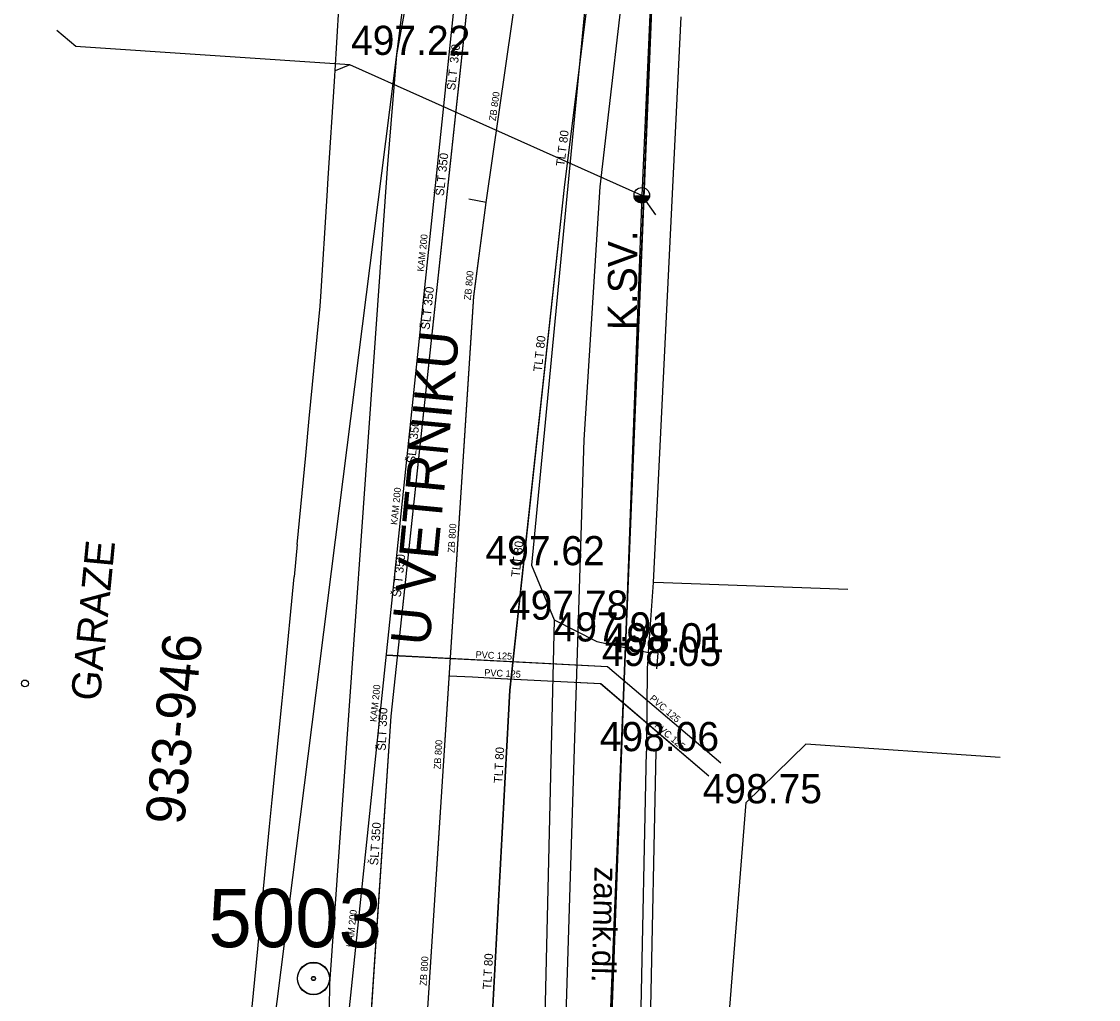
# Model space of a CAD drawing. Extents: x -669642 to -669119, y -1131006 to -1130466.
# Drawn here: x -669414.71 to -669387.02, y -1130677.82 to -1130652.68 of the extents above; entities that cross this region are included whole.
import ezdxf

# ---------------------------------------------------------------- set-up
doc = ezdxf.new("R2010")
doc.units = 0
for name, color, linetype in [('G_Bod_tecka', 7, 'Continuous'), ('G_Bod_vyska', 7, 'Continuous'), ('G_Bodove_pole', 7, 'Continuous'), ('G_Budovy-znacky', 7, 'Continuous'), ('G_Budovy_Objekty', 7, 'Continuous'), ('G_Budovy_vstupy', 7, 'Continuous'), ('G_Cisla_jina', 7, 'Continuous'), ('G_Plochy_zpevnene', 7, 'Continuous'), ('G_Ploty', 7, 'Continuous'), ('G_Ploty_vstupy', 7, 'Continuous'), ('G_Popisy_Nazvy', 7, 'Continuous'), ('G_Popisy_povrchu', 7, 'Continuous'), ('G_Poznamky_odkaz', 7, 'Continuous'), ('G_Site-Sloupy', 7, 'Continuous'), ('G_Z_ELsilove_nadz_kotovane', 7, 'Continuous'), ('G_Z_ELsilove_podz_kotovane', 7, 'Continuous'), ('G_Z_KANAL_podz_kotovane', 7, 'Continuous'), ('G_Z_KANAL_podz_priblizne', 7, 'Continuous'), ('G_Z_PLYNY_podz_geodeticky', 7, 'Continuous'), ('G_Z_SPOJE_nadz_kotovane', 7, 'Continuous'), ('G_Z_VODA_podz_kotovane', 7, 'Continuous'), ('Vrstva 11', 7, 'Continuous'), ('Vrstva 12', 7, 'Continuous'), ('Vrstva 26', 7, 'Continuous'), ('Vrstva 3', 7, 'Continuous'), ('Vrstva 4', 7, 'Continuous'), ('Vrstva 5', 7, 'Continuous'), ('Vrstva 9', 7, 'Continuous')]:
    doc.layers.add(name, color=color, linetype=linetype)

msp = doc.modelspace()

# ---------------------------------------------------------------- linework, layer by layer
at = {"layer": 'G_Bod_tecka'}
for p, q in [((-669405.07, -1130653.54), (-669405.07, -1130653.54)), ((-669401.6, -1130666.66), (-669401.6, -1130666.66)), ((-669401.01, -1130668.06), (-669401.01, -1130668.06)), ((-669399.92, -1130668.62), (-669399.92, -1130668.62)), ((-669398.59, -1130668.9), (-669398.59, -1130668.9)), ((-669398.6, -1130669.25), (-669398.6, -1130669.25)), ((-669398.64, -1130671.44), (-669398.64, -1130671.44)), ((-669396.03, -1130672.78), (-669396.03, -1130672.78))]:
    msp.add_line(p, q, dxfattribs=at)
at = {"layer": 'G_Bodove_pole'}
for centre, radius in [((-669407.2, -1130677.28), 0.412), ((-669407.2, -1130677.29), 0.412), ((-669407.2, -1130677.28), 0.05), ((-669407.2, -1130677.29), 0.05)]:
    msp.add_circle(centre, radius, dxfattribs=at)
at = {"layer": 'G_Budovy-znacky'}
msp.add_circle((-669414.62, -1130669.699), 0.0875, dxfattribs=at)
at = {"layer": 'G_Budovy_Objekty'}
for p, q in [((-669406.66, -1130654.22), (-669406.61, -1130653.37)), ((-669406.85, -1130657.16), (-669406.82, -1130656.71)), ((-669407.03, -1130660), (-669407.01, -1130659.75)), ((-669407.06, -1130660.35), (-669407.03, -1130660)), ((-669407.4, -1130663.84), (-669407.31, -1130662.89)), ((-669407.62, -1130666.13), (-669407.7, -1130666.96)), ((-669408.01, -1130670.15), (-669407.95, -1130669.55)), ((-669396.08, -1130672.76), (-669394.54, -1130671.26)), ((-669389.55, -1130671.6), (-669394.54, -1130671.26)), ((-669408.33, -1130673.38), (-669408.26, -1130672.69)), ((-669396.63, -1130679.75), (-669396.08, -1130672.76)), ((-669408.63, -1130676.52), (-669408.57, -1130675.87))]:
    msp.add_line(p, q, dxfattribs=at)
at = {"layer": 'G_Budovy_vstupy'}
for p, q in [((-669406.61, -1130653.37), (-669406.46, -1130650.92)), ((-669406.82, -1130656.71), (-669406.66, -1130654.22)), ((-669407.01, -1130659.75), (-669406.85, -1130657.16)), ((-669407.31, -1130662.89), (-669407.06, -1130660.35)), ((-669407.62, -1130666.13), (-669407.4, -1130663.84)), ((-669407.95, -1130669.55), (-669407.7, -1130666.96)), ((-669408.26, -1130672.69), (-669408.01, -1130670.15)), ((-669408.57, -1130675.87), (-669408.33, -1130673.38)), ((-669408.87, -1130678.96), (-669408.63, -1130676.52))]:
    msp.add_line(p, q, dxfattribs=at)
at = {"layer": 'G_Plochy_zpevnene'}
for points in [[(-669403.74, -1130646.37), (-669404.42, -1130649.99), (-669405.07, -1130653.54)], [(-669400.06, -1130650.63), (-669401.6, -1130666.66)], [(-669405.07, -1130653.54), (-669405.31, -1130656.46)], [(-669405.31, -1130656.46), (-669406.79, -1130677.42)], [(-669401.6, -1130666.66), (-669401.01, -1130668.06)], [(-669401.01, -1130668.06), (-669401.52, -1130689.56), (-669401.73, -1130703.06)], [(-669401.01, -1130668.06), (-669399.92, -1130668.62)], [(-669399.92, -1130668.62), (-669398.59, -1130668.9)], [(-669406.79, -1130677.42), (-669407.03, -1130695.18)]]:
    msp.add_lwpolyline(points, dxfattribs=at)
at = {"layer": 'G_Ploty'}
for p, q in [((-669398.05, -1130658.69), (-669397.75, -1130652.56)), ((-669398.46, -1130667.1), (-669398.05, -1130658.69)), ((-669398.59, -1130668.9), (-669398.46, -1130667.1)), ((-669398.2, -1130667.11), (-669398.46, -1130667.1)), ((-669393.46, -1130667.28), (-669398.2, -1130667.11)), ((-669398.59, -1130668.9), (-669398.62, -1130669.3)), ((-669398.34, -1130668.92), (-669398.59, -1130668.9)), ((-669398.37, -1130669.32), (-669398.34, -1130668.92)), ((-669398.81, -1130679.62), (-669398.64, -1130671.44)), ((-669398.56, -1130679.63), (-669398.39, -1130671.44))]:
    msp.add_line(p, q, dxfattribs=at)
at = {"layer": 'G_Ploty_vstupy'}
msp.add_line((-669398.62, -1130669.3), (-669398.64, -1130671.44), dxfattribs=at)
at = {"layer": 'G_Site-Sloupy'}
msp.add_circle((-669398.76, -1130657.15), 0.2, dxfattribs=at)
for radius in [0.18, 0.16, 0.14, 0.12, 0.1, 0.08, 0.06, 0.04, 0.02]:
    msp.add_arc((-669398.76, -1130657.15), radius, 180, 0, dxfattribs=at)
at = {"layer": 'G_Z_ELsilove_nadz_kotovane'}
for points in [[(-669397.335, -1130624.981), (-669398.76, -1130657.15)], [(-669413.315, -1130653.325), (-669413.8, -1130652.911)], [(-669398.76, -1130657.15), (-669406.265, -1130653.792), (-669413.316, -1130653.324)], [(-669406.265, -1130653.792), (-669406.644, -1130653.951)], [(-669398.76, -1130657.15), (-669399.972, -1130690.325)], [(-669398.76, -1130657.15), (-669398.409, -1130657.65)]]:
    msp.add_lwpolyline(points, dxfattribs=at)
at = {"layer": 'G_Z_ELsilove_podz_kotovane'}
msp.add_lwpolyline([(-669397.44, -1130624.27), (-669398.48, -1130651.54), (-669400.06, -1130690.34), (-669400.27, -1130706.05), (-669396.56, -1130732.21), (-669391.83, -1130758.66)], dxfattribs=at)
at = {"layer": 'G_Z_KANAL_podz_kotovane'}
for p, q in [((-669407.69, -1130691.54), (-669402.63, -1130643.21)), ((-669402.76, -1130657.33), (-669403.21, -1130657.25)), ((-669405.54, -1130697.79), (-669403.08, -1130659.75))]:
    msp.add_line(p, q, dxfattribs=at)
for points in [[(-669403.08, -1130659.75), (-669402.76, -1130657.33), (-669401.92, -1130651.49)], [(-669396.73, -1130671.75), (-669399.64, -1130669.27), (-669405.33, -1130668.98)]]:
    msp.add_lwpolyline(points, dxfattribs=at)
at = {"layer": 'G_Z_KANAL_podz_priblizne'}
msp.add_lwpolyline([(-669397.04, -1130672.08), (-669399.82, -1130669.71), (-669402.38, -1130669.58), (-669403.11, -1130669.54), (-669403.71, -1130669.51)], dxfattribs=at)
at = {"layer": 'G_Z_PLYNY_podz_geodeticky'}
msp.add_lwpolyline([(-669393.28, -1130633.86), (-669394.49, -1130638.18), (-669399.08, -1130650.34), (-669399.84, -1130656.93), (-669400.25, -1130663.44), (-669400.87, -1130683.15), (-669400.96, -1130685.74), (-669400.98, -1130689.56)], dxfattribs=at)
at = {"layer": 'G_Z_SPOJE_nadz_kotovane'}
msp.add_lwpolyline([(-669403.46, -1130640.77), (-669408.34, -1130679.44)], dxfattribs=at)
at = {"layer": 'G_Z_VODA_podz_kotovane'}
for points in [[(-669387.02, -1130812.53), (-669389.23, -1130792.08), (-669391, -1130779.42), (-669391.97, -1130772.22), (-669392.06, -1130771.92), (-669391.97, -1130771.16), (-669393.13, -1130764.98), (-669393.69, -1130761.37), (-669394.75, -1130753.04), (-669396.24, -1130745.91), (-669399.34, -1130731.13), (-669400.46, -1130726.23), (-669400.61, -1130725.04), (-669400.78, -1130724.52), (-669402.59, -1130713.28), (-669402.7, -1130712.61), (-669402.95, -1130701.47), (-669402.25, -1130693.89), (-669402.71, -1130680.24), (-669402.15, -1130669.87), (-669400.75, -1130656.95), (-669398.85, -1130641.75)], [(-669403.09, -1130650.73), (-669405.21, -1130670.54), (-669406.48, -1130689.47), (-669407.14, -1130697.84), (-669406.32, -1130715.38), (-669403.7, -1130729.64), (-669400.71, -1130745.88), (-669399.15, -1130753.32), (-669398.52, -1130755.36), (-669396.1, -1130756.91), (-669395.09, -1130760.49), (-669394.09, -1130765.4), (-669391.66, -1130786.81), (-669388.98, -1130811.25)]]:
    msp.add_lwpolyline(points, dxfattribs=at)
at = {"layer": 'Vrstva 11'}
msp.add_lwpolyline([(-669396.732, -1130671.751), (-669399.639, -1130669.272), (-669405.328, -1130668.975)], dxfattribs=at)
at = {"layer": 'Vrstva 12'}
for p, q in [((-669407.692, -1130691.538), (-669402.628, -1130643.211)), ((-669402.76, -1130657.33), (-669403.205, -1130657.246)), ((-669405.541, -1130697.793), (-669403.077, -1130659.745))]:
    msp.add_line(p, q, dxfattribs=at)
msp.add_lwpolyline([(-669403.077, -1130659.745), (-669402.76, -1130657.33), (-669401.92, -1130651.49)], dxfattribs=at)
at = {"layer": 'Vrstva 26'}
for points in [[(-669387.019, -1130812.528), (-669389.231, -1130792.082), (-669391.001, -1130779.42), (-669391.97, -1130772.22), (-669392.06, -1130771.92), (-669391.97, -1130771.16), (-669393.133, -1130764.977), (-669393.689, -1130761.37), (-669394.75, -1130753.038), (-669396.244, -1130745.914), (-669399.343, -1130731.135), (-669400.461, -1130726.23), (-669400.612, -1130725.037), (-669400.78, -1130724.52), (-669402.594, -1130713.284), (-669402.695, -1130712.614), (-669402.948, -1130701.466), (-669402.247, -1130693.89), (-669402.705, -1130680.236), (-669402.147, -1130669.872), (-669400.746, -1130656.946), (-669398.853, -1130641.75)], [(-669403.087, -1130650.733), (-669405.214, -1130670.54), (-669406.476, -1130689.467), (-669407.14, -1130697.842), (-669406.32, -1130715.384), (-669403.695, -1130729.64), (-669400.705, -1130745.879), (-669399.153, -1130753.32), (-669398.519, -1130755.364), (-669396.099, -1130756.914), (-669395.09, -1130760.491), (-669394.091, -1130765.401), (-669391.664, -1130786.81), (-669388.978, -1130811.253)]]:
    msp.add_lwpolyline(points, dxfattribs=at)
at = {"layer": 'Vrstva 5'}
for p, q in [((-669398.48, -1130651.54), (-669400.06, -1130690.34)), ((-669400.06, -1130690.34), (-669398.48, -1130651.54))]:
    msp.add_line(p, q, dxfattribs=at)
at = {"layer": 'Vrstva 9'}
msp.add_lwpolyline([(-669397.04, -1130672.082), (-669399.817, -1130669.713), (-669402.384, -1130669.579), (-669403.109, -1130669.541), (-669403.709, -1130669.51)], dxfattribs=at)

# ---------------------------------------------------------------- texts
at = {"layer": 'G_Bod_vyska'}
for s, p in [('497.22', (-669406.236, -1130653.54)), ('497.62', (-669402.78, -1130666.66)), ('497.78', (-669402.176, -1130668.06)), ('497.91', (-669401.026, -1130668.62)), ('498.01', (-669399.716, -1130668.9)), ('498.05', (-669399.788, -1130669.25)), ('498.06', (-669399.841, -1130671.44)), ('498.75', (-669397.196, -1130672.78))]:
    msp.add_text(s, height=0.75, dxfattribs=at).set_placement(p)
at = {"layer": 'G_Bodove_pole'}
msp.add_text('5003', height=1.5, dxfattribs=at).set_placement((-669409.903, -1130676.48))
at = {"layer": 'G_Cisla_jina'}
msp.add_text('933-946', height=1, rotation=84.5231, dxfattribs=at).set_placement((-669410.529, -1130673.353))
at = {"layer": 'G_Popisy_Nazvy'}
msp.add_text('U VETRNIKU', height=1, rotation=84.5281, dxfattribs=at).set_placement((-669404.224, -1130668.754))
at = {"layer": 'G_Popisy_povrchu'}
msp.add_text('zamk.dl.', height=0.6, rotation=268.5879, dxfattribs=at).set_placement((-669399.975, -1130674.404))
at = {"layer": 'G_Poznamky_odkaz'}
for s, rotation, p in [('K.SV.', 89.7299, (-669398.887, -1130660.616)), ('GARAZE', 84.5231, (-669412.694, -1130670.167))]:
    msp.add_text(s, height=0.75, rotation=rotation, dxfattribs=at).set_placement(p)
at = {"layer": 'Vrstva 3'}
for s, rotation, p in [('ZB 800', 82.0565, (-669402.517, -1130655.248)), ('KAM 200', 84.0331, (-669404.365, -1130659.118)), ('ZB 800', 84.3076, (-669403.158, -1130659.852)), ('KAM 200', 84.0365, (-669405.048, -1130665.63)), ('ZB 800', 86.2642, (-669403.576, -1130666.347)), ('PVC 125', 357.0238, (-669403.037, -1130669.042)), ('PVC 125', 357.0051, (-669402.814, -1130669.503)), ('KAM 200', 84.0365, (-669405.58, -1130670.696)), ('PVC 125', 319.5149, (-669398.575, -1130670.11)), ('PVC 125', 319.5279, (-669398.45, -1130670.809)), ('ZB 800', 86.3021, (-669403.935, -1130671.91)), ('KAM 200', 84.0398, (-669406.186, -1130676.486)), ('ZB 800', 86.3047, (-669404.296, -1130677.474))]:
    msp.add_text(s, height=0.1755, rotation=rotation, dxfattribs=at).set_placement(p)
at = {"layer": 'Vrstva 4'}
for s, rotation, p in [('ŠLT  350', 83.8397, (-669403.559, -1130654.458)), ('TLT 80', 82.9439, (-669400.751, -1130656.412)), ('ŠLT 350', 83.9054, (-669403.85, -1130657.175)), ('ŠLT 350', 83.8769, (-669404.219, -1130660.613)), ('TLT 80', 83.8271, (-669401.332, -1130661.693)), ('ŠLT 350', 83.9069, (-669404.588, -1130664.051)), ('TLT 80', 83.8606, (-669401.904, -1130666.974)), ('ŠLT 350', 83.8784, (-669404.958, -1130667.489)), ('ŠLT 350', 87.6516, (-669405.345, -1130671.434)), ('TLT 80', 86.8996, (-669402.347, -1130672.268)), ('ŠLT 350', 86.1831, (-669405.541, -1130674.382)), ('TLT 80', 86.9686, (-669402.632, -1130677.573))]:
    msp.add_text(s, height=0.2194, rotation=rotation, dxfattribs=at).set_placement(p)

doc.saveas('drawing.dxf')
